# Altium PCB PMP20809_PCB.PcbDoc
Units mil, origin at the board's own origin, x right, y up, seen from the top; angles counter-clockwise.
Board outline 3600 x 1460 mil, 2 copper layers (Top Layer, Bottom Layer), stack 62 mil thick; 44 components, 29 nets, 110 pads, 38 vias.
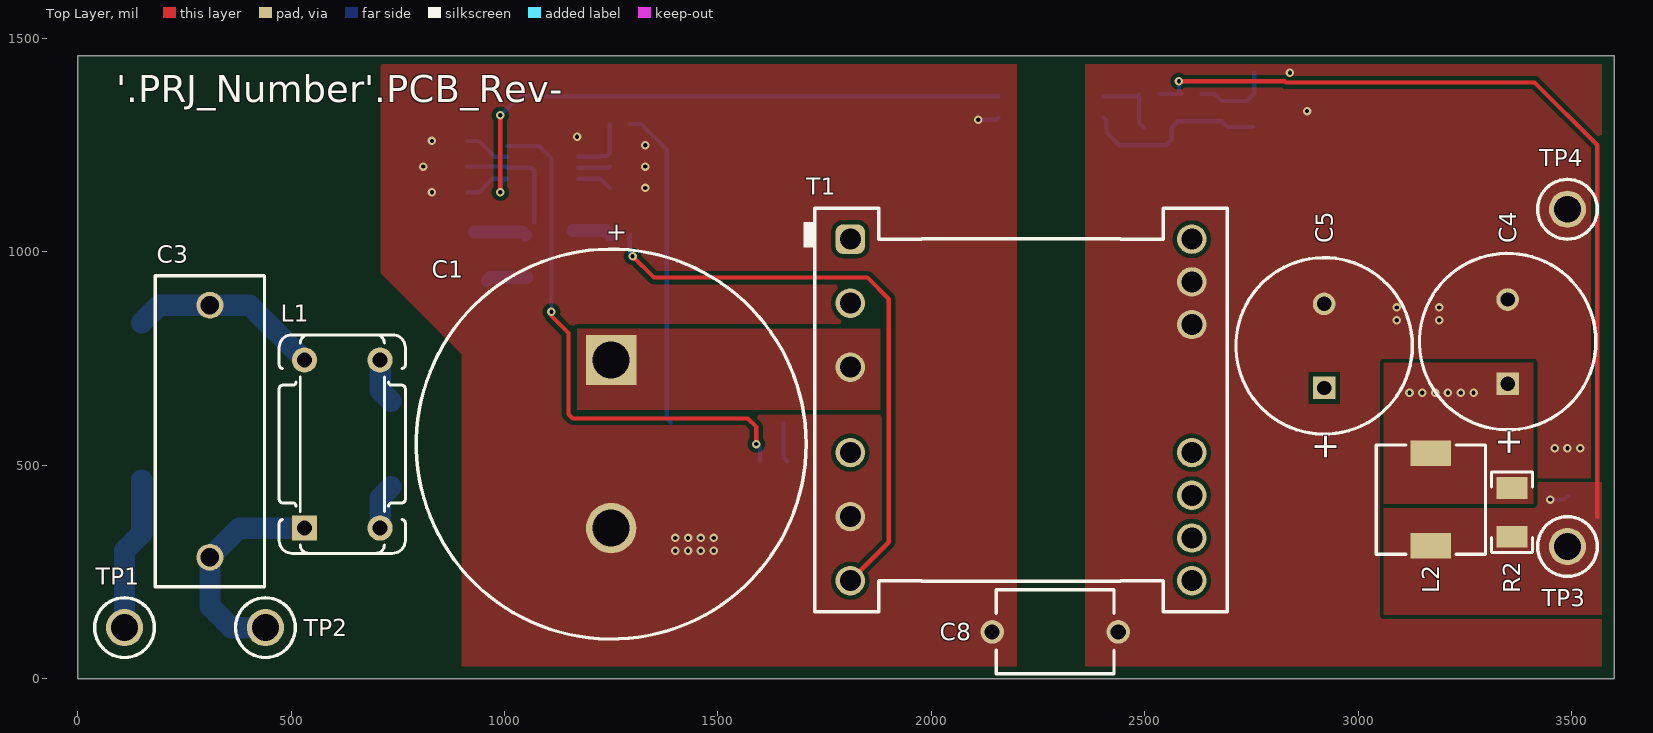
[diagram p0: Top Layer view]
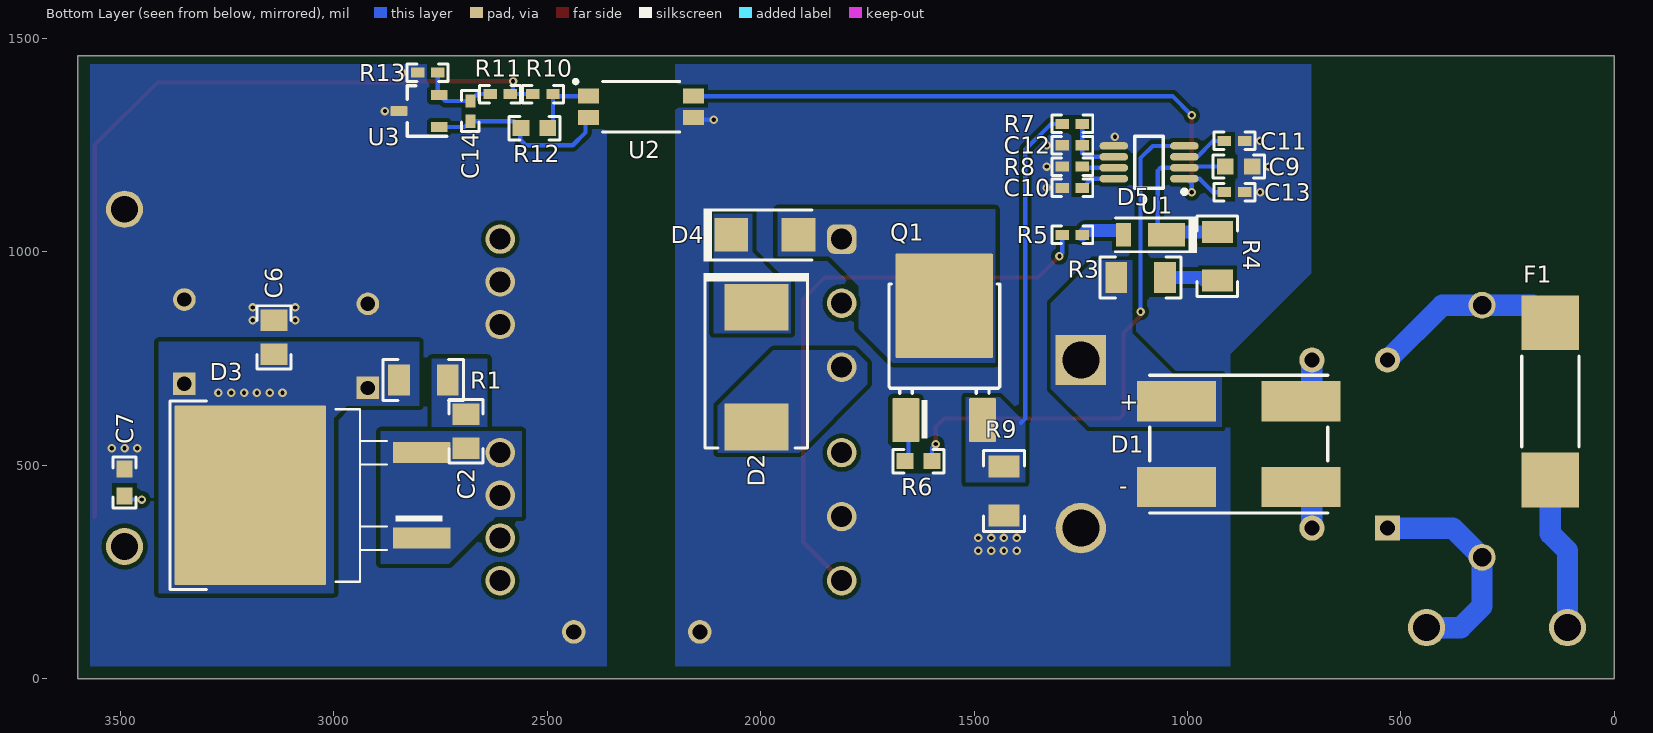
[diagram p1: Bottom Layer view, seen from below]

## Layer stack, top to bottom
Top Solder: solder mask 0.4, Solder Resist, Dk 3.5
Top Layer: signal copper 1.4
Dielectric1: core 59.2, FR-4, Dk 4.8
Bottom Layer: signal copper 1.4
Bottom Solder: solder mask 0.4, Solder Resist, Dk 3.5

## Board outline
0,0 3600,0 3600,1460 0,1460

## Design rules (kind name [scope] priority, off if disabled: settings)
AcuteAngle [All] p1: minimum=4.50000000000000E+0001 checktracksonly=FALSE
AssemblyTestPointUsage [All] p1: valid=2
Clearance Clearance_BoardEdge_MountingHoles [OnCopper and InComponentClass('Mounting Holes') vs IsKeepOut] p1: gap=40
Clearance Clearance_BoardEdge_Poly [OnCopper and InPoly vs IsKeepOut] p2: gap=25
Clearance Clearance_BoardEdge [OnCopper and Not InComponentClass('Logo') and not InComponentClass('FiducialMark') and not InRegion(1000,500,4000,800) and Not IsKeepout vs IsKeepOut] p3: gap=75
Clearance Clearance_Poly [InPolygon] p4: gap=10
Clearance [All] p5: gap=8
ComponentClearance ComponentClearance_ScrewToNut [(HasFootprint('NY PMS 440 0025 PH')) vs (HasFootprint('Keystone_1902C'))] p1: gap=5 collisioncheckmode=3 verticalgap=10 showdistances=FALSE
ComponentClearance ComponentClearance_MountingHoles [InComponentClass('Mounting Holes')] p2: gap=20 collisioncheckmode=3 verticalgap=100000 showdistances=FALSE
ComponentClearance ComponentClearance_SmallPassives [HasFootprint('0201*') or HasFootprint('0402*') or HasFootprint('0508') or HasFootprint('0603*') or HasFootprint('0612') or HasFootprint('0805*') or HasFootprint('0815*') or HasFootprint('0830*') or HasFootprint('1206*') or HasFootprint('1210*') or HasFootprint('1808*') or HasFootprint('1812*') or HasFootprint('1825*') or HasFootprint('2010*') or HasFootprint('2220*') or HasFootprint('2225*') or HasFootprint('2512*') or HasFootprint('2728*') or HasFootprint('3518*') vs HasFootprint('0201*') or HasFootprint('0402*') or HasFootprint('0508') or HasFootprint('0603*') or HasFootprint('0612') or HasFootprint('0805*') or HasFootprint('0815*') or HasFootprint('0830*') or HasFootprint('1206*') or HasFootprint('1210*') or HasFootprint('1808*') or HasFootprint('1812*') or HasFootprint('1825*') or HasFootprint('2010*') or HasFootprint('2220*') or HasFootprint('2225*') or HasFootprint('2512*') or HasFootprint('2728*') or HasFootprint('3518*')] p3: gap=10 collisioncheckmode=3 verticalgap=10 showdistances=FALSE
ComponentClearance ComponentClearance_THtoSMT [IsThruComponent vs IsSMTComponent] p4: gap=20 collisioncheckmode=3 verticalgap=100000 showdistances=FALSE
ComponentClearance ComponentClearance_THtoTH [IsThruComponent vs IsThruComponent] p5: gap=20 collisioncheckmode=3 verticalgap=100000 showdistances=FALSE
ComponentClearance [All] p6: gap=20 collisioncheckmode=3 verticalgap=10 showdistances=FALSE
DiffPairsRouting [All] p1: maxlimit=100 minlimit=10 mostfreqgap=10 toplayer_minwidth=15 toplayer_maxwidth=15 toplayer_prefwidth=15 bottomlayer_minwidth=15 bottomlayer_maxwidth=15 bottomlayer_prefwidth=15 maxuncoupledlength=1000
FabricationTestPointUsage TestPointUsage [All] p1: valid=2 allowmultiple=FALSE
FabricationTestpoint Testpoint [All] p1: side=3 testpointundercomponent=TRUE minsize=40 maxsize=100 preferedsize=60 minholesize=0 maxholesize=40 preferedholesize=32 testpointgrid=1 allowsidetop=TRUE allowsidebottom=TRUE usegrid=TRUE gridtolerance=0.01
FanoutControl Fanout_LCC [IsLCC] p1: bgadir=Out bgaviamode=Centered fanoutstyle=Auto fanoutdirection=Alternating viagrid=1 // Fanout_LCC (Default Rule)
FanoutControl Fanout_BGA [IsBGA] p2: bgadir=Out bgaviamode=Centered fanoutstyle=Auto fanoutdirection=Alternating viagrid=1 // Fanout_BGA (Default Rule)
FanoutControl Fanout_Default [All] p4: bgadir=Out bgaviamode=Centered fanoutstyle=Auto fanoutdirection=Alternating viagrid=1 // Fanout_Default (Default Rule)
FanoutControl Fanout_Small [(CompPinCount < 5)] p5: bgadir=Out bgaviamode=Centered fanoutstyle=Auto fanoutdirection=OutThenIn viagrid=1 // Fanout_Small (Default Rule)
HoleSize [All] p1: absolutevalues=TRUE maxlimit=251 minlimit=7 maxpercent=80.000 minpercent=20.000
MinimumAnnularRing [All] p1: minimumring=5
MinimumSolderMaskSliver MinimumSolderMaskSliver_Logo [InComponentClass('Logo') vs InComponentClass('Logo')] p1: minsoldermaskwidth=0
MinimumSolderMaskSliver SilkscreenOverComponentPads [All] p2: minsoldermaskwidth=0
MinimumSolderMaskSliver [All] p3: minsoldermaskwidth=0
PlaneConnect [All] p1: planeconnectstyle=Direct reliefexpansion=10 reliefentries=4 reliefconductorwidth=10 reliefairgap=10
PolygonConnect [All] p1: connectstyle=Direct reliefconductorwidth=10 reliefentries=4 polygonreliefangle="90 Angle" airgapwidth=10
RoutingVias [All] p1: holewidth=16 width=34 viastyle="Through Hole" minholewidth=7 minwidth=19 maxholewidth=40 maxwidth=65
SMDToCorner [All] p1: distance=0
SilkToBoardRegionClearance [Not ((IsComment or IsDesignator) And (Hide <> 'False')) and not InRegion(1000,500,4000,800)] p1:
SilkToSilkClearance [All] p1: silktosilkclearance=0
SilkToSolderMaskClearance [IsPad] p1: minsilkscreentomaskgap=0 clearancetoexposedcopper=TRUE
SolderMaskExpansion [All] p1: expansion=3
Width [All] p1: maxlimit=100 minlimit=6 preferedwidth=10 checkconnectedcopper=TRUE
15 further rules are at their usual default settings.

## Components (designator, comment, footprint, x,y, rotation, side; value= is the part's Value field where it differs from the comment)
C1 "LLS2G820MELZ" Nichicon_2200x2500_Snap 1250,550 r270 top
C2 "GRM2165C1H101JA01D" 0805_HV 2690,580 r270 bottom
C3 "890324025017" WCAP-FTX2_1800x600x1200 310,580 r270 top
C4 "EKZE350ELL221MJC5S" Chemi-Con_1000x1250 3350,790 r90 top
C5 "EKZE350ELL221MJC5S" Chemi-Con_1000x1250 2920,780 r90 top
C6 "C2012X5R1V685K125AC" 0805_HV 3140,800 r90 bottom
C7 "C1608X5R1H104K080AA" 0603 3490,460 r90 bottom
C8 "DE2E3KY152MN3AM02F" KY_700x500x1000 2290,110 r180 top
C9 "GRM188R6YA106MA73" 0603 880,1200 r180 bottom
C10 "GRM155R71C224KA12D" 0402 1270,1150 r0 bottom
C11 "GRM155R61E105KA12D" 0402 890,1260 r180 bottom
C12 "GRM1555C1H101JA01D" 0402 1270,1250 r0 bottom
C13 "GRM1555C1H101JA01D" 0402 890,1140 r180 bottom
C14 "GRM155R71H103KA88D" 0402 2680,1330 r270 bottom
D1 "Z4DGP406L-HF" Z4-D 880,550 r180 bottom
D2 "SMCJ150A-TP" SMC 2010,730 r270 bottom
D3 "MBRB20200CTT4G" DDPAK 3040,430 r0 bottom
D4 "MURA160T3G" SMA 1990,1040 r180 bottom
D5 "DFLS1200-7" PowerDI123 1099.8,1040 r0 bottom
F1 "0443003.DR" FUSE_0443 150,650 r270 bottom
L1 "744821201" WE-CMB_XS 620,550 r90 top
L2 "B82462G4102M" B82462G4 3170,420 r270 top
Q1 "AOD4S60" DPAK 1570,740 r90 bottom
R1 "CRCW1206100RJNEA" 1206 2790,700 r0 bottom
R2 "CRCW12062R00FKEA" 1206 3360,390 r270 top
R3 "CRCW1206499KFKEA" 1206 1110,940 r0 bottom
R4 "CRCW1206499KFKEA" 1206 930,990 r270 bottom
R5 "CRCW04020000Z0ED" 0402 1270,1040 r0 bottom
R6 "CRCW06030000Z0EA" 0603 1630,510 r0 bottom
R7 "CRCW04021K00JNED" 0402 1270,1300 r0 bottom
R8 "CRCW040222K1FKED" 0402 1270,1200 r180 bottom
R9 "CSR1206FKR250" 1206 1430,440 r90 bottom
R10 "CRCW04024K99FKED" 0402 2510,1370 r0 bottom
R11 "CRCW0402162KFKED" 0402 2610,1370 r180 bottom
R12 "CRCW06031K00JNEA" 0603 2530,1290 r180 bottom
R13 "CRCW040218K7FKED" 0402 2780,1420 r180 bottom
T1 "RLTI-1228" Renco_RLTI-1228 2210,630 r0 top
TP1 "5012" Keystone5012 110,120 r90 top
TP2 "5012" Keystone5012 440,120 r90 top
TP3 "5010" Keystone5010 3490,310 r0 top
TP4 "5011" Keystone5011 3490,1100 r0 top
U1 "LM5021MM-2/NOPB" MUA08A_N 1090,1210 r0 bottom
U2 "VOS617A-7X001T" SSOP-4_VISHAY 2280,1340 r180 bottom
U3 "TL431AIDBZR" DBZ0003A_N 2800,1330 r0 bottom

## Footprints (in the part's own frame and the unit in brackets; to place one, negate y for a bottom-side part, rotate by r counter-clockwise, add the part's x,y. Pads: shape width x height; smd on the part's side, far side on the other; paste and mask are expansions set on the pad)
0402 [mm] "0402 from SM-752 data"
  rect 0.8x0.6 smd: 1(-0.6,0) 2(0.6,0)
  silkscreen extent -1.22,-0.52 1.22,0.52, body extent -0.55,-0.3 0.55,0.3, height 0.6
0603 [mm] "0603 from SM-752 data"
  rect 1x0.95 smd: 1(-0.8,0) 2(0.8,0)
  silkscreen extent -1.52,-0.69 1.52,0.69, body extent -0.87,-0.47 0.87,0.47, height 1
0805_HV [mil] "0805 with 30mil clearance between pads"
  rect 50x63 smd: 1(-40,0) 2(40,0)
  silkscreen extent -74,-40 74,40, body extent -43,-29 43,29, height 57
1206 [mm] "1206 from SM-752 data"
  rect 1.3x1.85 smd: 1(-1.45,0) 2(1.45,0)
  silkscreen extent -2.4,-1.21 2.4,1.21, body extent -1.7,-0.9 1.7,0.9, height 1.35
B82462G4 [mm] "EPCOS"
  rect 1.5x2.4 smd: 1(-2.75,0) 2(2.75,0)
  silkscreen extent -3.25,-3.25 3.25,3.25, body extent -3.15,-3.15 3.15,3.15, height 3
Chemi-Con_1000x1250 [mm] "TH, 2-Leads, Body 10x12.5mm, Pin Spacing 5mm"
  rect 1.35x1.35 hole 0.85: 1(-2.5,0)
  round 1.35 hole 0.85: 2(2.5,0)
  silkscreen extent -5.25,-5.25 5.25,5.25, body extent -5.25,-5.25 5.25,5.25, height 14
DBZ0003A_N [mm] "SOT23, 3-Leads, Body 2.9x1.3mm, Pitch 0.95mm, Lead Span 2.4mm, IPC Medium Density"
  rrect17% 1x0.6 smd: 1(-1.2,0.95) 2(-1.2,-0.95) 3(1.2,0)
  silkscreen extent -1.65,-1.5 0.7,1.5, body extent -1.26,-1.46 1.26,1.46, height 0.98
DDPAK [mil] "D2-PAK, 3-Pads, Body 9.7x10.4mm (max), TO-263AB, using Vishay Silionix recommended pad sizes"
  rrect8% 135x49.49 smd: 1(-246.06,100) 3(-246.06,-100)
  rrect1% 355x420 smd paste-181.1: 4(155.51,0)
  silkscreen extent -295,-220 344,220, body extent -295,-202 324,202, height 180
DPAK [mm] "D-PAK, 3-Pads, Body 6.22x6.73mm (max), TO-252AA using nominal STEP model"
  rrect6% 2.6x1.6 smd: 1(-3.4,2.28) 3(-3.4,-2.28)
  rrect2% 6.2x5.8 smd paste-2.9: 4(3.4,0)
  silkscreen extent -4.5,-3.3 4.7,3.28, body extent -3.86,-3.29 5.84,3.29, height 2.48
FUSE_0443 [mm] "LITTELFUSE"
  rect 3.25x3.43 smd: 1(-4.675,0) 2(4.675,0)
  silkscreen extent -2.7,-1.7 2.7,1.7, body extent -5.05,-1.56 5.05,1.56, height 3.12
Keystone5010 [mil] "Keystone Multipurpose loops"
  round 87 hole 63: 1(0,0)
  silkscreen extent -70,-70 70,70, body extent -63,-63 63,62, height 319
Keystone5011 [mil] "Keystone Multipurpose loops"
  round 87 hole 63: 1(0,0)
  silkscreen extent -70,-70 70,70, body extent -63,-63 63,62, height 319
Keystone5012 [mil] "Keystone Multipurpose loops"
  round 87 hole 63: 1(0,0)
  silkscreen extent -70,-70 70,70, body extent -63,-63 63,62, height 319
KY_700x500x1000 [mm] "TH, 2- Leads, Body 7x5mm, Pin Spacing 7.5mm"
  round 1.4 hole 0.9: 1(-3.75,0) 2(3.75,0)
  silkscreen extent -3.5,-2.5 3.5,2.5, body extent -4.05,-2.5 4.05,2.5, height 9.97
MUA08A_N [mm] "TSOP, 8-Leads, Body 3x3mm, Pitch 0.65mm, IPC Medium Density"
  oval 1.7x0.45 smd: 1(-2.1,0.975) 2(-2.1,0.325) 3(-2.1,-0.325) 4(-2.1,-0.975) 5(2.1,-0.975) 6(2.1,-0.325) 7(2.1,0.325) 8(2.1,0.975)
  silkscreen extent -2.22,-1.55 0.85,1.87, body extent -1.6,-1.6 1.6,1.6, height 1.09
Nichicon_2200x2500_Snap [mm]
  rrect3% 3x3 hole 2.2: 1(-5,0)
  round 3 hole 2.2: 2(5,0)
  silkscreen extent -11.6,-11.6 11.6,11.6, body extent -11.5,-11.5 11.51,11.5, height 27.01
PowerDI123 [mm] "Diodes Inc recommended land pattern, document number DS30628 Rev. 6-2"
  rect 2.2x1.4 smd: 1(-1.275,0)
  rect 0.9x1.4 smd: 2(1.275,0)
  silkscreen extent -3.1,-1.09 1.76,1.09, body extent -2.37,-0.96 1.53,0.97, height 1
Renco_RLTI-1228 [mm] "TH, 13-Leads, Body 966x945mil"
  rrect50% 1.75x1.75 hole 1.25: 1(-10.16,10.16)
  round 1.75 hole 1.25: 2(-10.16,6.35) 3(-10.16,2.54) 4(-10.16,-2.54) 5(-10.16,-6.35) 6(-10.16,-10.16) 7(10.16,-10.16) 8(10.16,-7.62) 9(10.16,-5.08) 10(10.16,-2.54) 12(10.16,5.08) 13(10.16,7.62) 14(10.16,10.16)
  silkscreen extent -12.95,-12 12.27,12, body extent -12.27,-12 12.27,12, height 23.49
SMA [mm] "Molded Diode, 2-Leads, Body 4.3x2.6mm, IPC Medium Density, based on OnSemi component dimensions and land pattern"
  rect 2x2 smd: 1(-2,0) 2(2,0)
  silkscreen extent -3.66,-1.57 2.79,1.57, body extent -2.6,-1.3 2.6,1.3, height 2.42
SMC [mil] "Molded Diode, 2-Leads, Body 6.9x5.8mm, IPC Medium Density, based on OnSemi component dimensions and land patterns"
  rect 110x150 smd: 1(-140.49,0) 2(140.49,0)
  silkscreen extent -221,-123 189,124, body extent -156,-116 157,116, height 91
SSOP-4_VISHAY [mm] "Vishay Recommened"
  rect 1.25x0.9 smd: 1(-3.125,0.635) 2(-3.125,-0.635) 3(3.125,-0.635) 4(3.125,0.635)
  silkscreen extent -3.98,-1.5 2.3,1.59, body extent -3.5,-1.45 3.5,1.45, height 2.42
WCAP-FTX2_1800x600x1200 [mm] "TH, 2-Leads, Body 18x6mm, Lead Spacing 15mm"
  round 1.6 hole 1.1: 1(-7.5,0) 2(7.5,0)
  silkscreen extent -9.25,-3.25 9.25,3.25, body extent -9.25,-3.25 9.25,3.25, height 12.5
WE-CMB_XS [mm] "WE-CMB Series Size XS"
  rect 1.5x1.5 hole 0.9: 1(-5,2.25)
  round 1.5 hole 0.9: 2(-5,-2.25) 3(5,-2.25) 4(5,2.25)
  silkscreen extent -6.5,-3.75 6.5,3.75, body extent -6.5,-3.75 6.5,3.75, height 16.24
Z4-D [mm] "SMD, 4-Leads, Body 8.1x10.5mm"
  rect 4.7x2.4 smd: 1(-3.7,2.55) 2(3.7,2.55) 3(3.7,-2.55) 4(-3.7,-2.55)
  silkscreen extent -5.3,-4.1 5.3,4.1, body extent -5.3,-4.1 5.3,4.1, height 1.56

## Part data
C1: "CAP, AL, 82 µF, 400 V, +/- 20%, TH"
C2: "CAP, CERM, 100 pF, 50 V, +/- 5%, C0G/NP0, 0805"
C3: "CAP, Film, 0.1 µF, 275 V, +/- 10%, TH"
C4 C5: "CAP, AL, 220 µF, 35 V, +/- 20%, TH"
C6: "CAP, CERM, 6.8 µF, 35 V, +/- 10%, X5R, 0805"
C7: "CAP, CERM, 0.1 µF, 50 V, +/- 10%, X5R, 0603"
C8: "CAP, CERM, 1500 pF,  V, +/- 20%, E, TH, 2- Leads, Body 7x5mm, Pin Spacing 7.5mm"
C9: "CAP, CERM, 10 µF, 35 V, +/- 20%, X5R, 0603"
C10: "CAP, CERM, 0.22 µF, 16 V, +/- 10%, X7R, 0402"
C11: "CAP, CERM, 1 µF, 25 V, +/- 10%, X5R, 0402"
C12 C13: "CAP, CERM, 100 pF, 50 V, +/- 5%, C0G/NP0, 0402"
C14: "CAP, CERM, 0.01 µF, 50 V, +/- 10%, X7R, 0402"
D1: "Diode, P-N-Bridge, 600 V, 4 A, Z4-D"
D2: "Diode, TVS, Uni, 150 V, 243 Vc, SMC"
D3: "Diode, Schottky, 200 V, 20 A, DDPAK"
D4: "Diode, Ultrafast, 600 V, 1 A, AEC-Q101, SMA"
D5: "Diode, Schottky, 200 V, 1 A, PowerDI123"
F1: "Fuse, 3 A, 250VAC/VDC, SMD"
L1: "Coupled inductor, 1 mH, 2 A, 0.045 ohm, TH"
L2: "Inductor, Shielded Drum Core, Ferrite, 1 µH, 3.4 A, 0.016 ohm, AEC-Q200 Grade 0, SMD"
Q1: "MOSFET, N-CH, 600 V, 4 A, DPAK"
R1: "RES, 100, 5%, 0.25 W, 1206"
R2: "RES, 2.00, 1%, 0.25 W, 1206"
R3 R4: "RES, 499 k, 1%, 0.25 W, 1206"
R5: "RES, 0, 5%, 0.063 W, 0402"
R6: "RES, 0, 5%, 0.1 W, 0603"
R7: "RES, 1.0 k, 5%, 0.063 W, 0402"
R8: "RES, 22.1 k, 1%, 0.063 W, 0402"
R9: "RES, 0.25, 1%, 0.5 W, 1206"
R10: "RES, 4.99 k, 1%, 0.063 W, 0402"
R11: "RES, 162 k, 1%, 0.063 W, 0402"
R12: "RES, 1.0 k, 5%, 0.1 W, 0603"
R13: "RES, 18.7 k, 1%, 0.063 W, 0402"
T1: "Transformer, 200 uH, TH"
TP1 TP2: "Test Point, Multipurpose, White, TH"
TP3: "Test Point, Multipurpose, Red, TH"
TP4: "Test Point, Multipurpose, Black, TH"
U1: "AC-DC Current Mode PWM Controller, 8-pin MSOP, Pb-Free"
U2: "Optocoupler, 3.75 kV, 80-160% CTR, SMT"
U3: "Adjustable Precision Shunt Regulator, 34 ppm / degC, 100 mA, -40 to 85 degC, 3-pin SOT-23 (DBZ), Green (RoHS & no Sb/Br)"

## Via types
v1: diameter 20, hole 10, Top Layer to Bottom Layer, tented both sides, 38 vias

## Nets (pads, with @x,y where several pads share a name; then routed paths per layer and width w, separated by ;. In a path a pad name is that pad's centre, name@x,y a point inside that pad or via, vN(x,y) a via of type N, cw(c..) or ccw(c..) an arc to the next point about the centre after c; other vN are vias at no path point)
24V: C7.1 L2.2 R2.2 R10.2 R11.2 TP3.1 | length 2041.1
  Top Layer w10: v1(2580,1400) 2827.47,1400 2830.47,1397 3413,1397 3560,1250 3560,380
  Bottom Layer w10: R10.2 R11.2 2580,1376.38 v1(2580,1400) ; v1(3450,420) 3481.5,420 C7.1
GND: C4.2 C5.2 C6.2 C7.2 C8.1 R13.1 T1.12 T1.13 TP4.1 U3.3
  other v1: 3460,540 3490,540 3520,540 3090,840 3190,840 3090,870 3190,870 2880,1330 2840,1420
NetC1_1: C1.1 D1.1 D2.2 R3.2 T1.3
NetC2_1: C2.1 R1.1
NetC2_2: C2.2 D3.1 D3.3 T1.9 T1.10
NetC3_1: C3.1 F1.1 L1.4 | length 451.7
  Bottom Layer w50: F1.1 191.22,875.28 C3.1 402.99,875.28 L1.4
NetC3_2: C3.2 L1.1 TP2.1 | length 515.2
  Bottom Layer w50: TP2.1 360,120 310,170 C3.2 378.43,353.15 L1.1
NetC4_1: C4.1 C5.1 C6.1 D3.4 L2.1 R1.2 R2.1
  other v1: 3120,670 3150,670 3180,670 3210,670 3240,670 3270,670
NetC9_1: C9.1 D5.1 R4.1 U1.2 | length 405.4
  Bottom Layer w10: C9.1 1004.53,1200 U1.2 1062.8,1197.2 1070,1190 1070,1069.8
  Bottom Layer w30: R4.1 1042.52,1047.09 D5.1
NetC10_1: C10.1 U1.8 | length 82.7
  Bottom Layer w10: U1.8 1224.76,1171.61 C10.1
NetC11_1: C11.1 U1.3 | length 109.1
  Bottom Layer w10: C11.1 940,1260 977.2,1222.8 U1.3
NetC12_1: C12.1 R7.1 U1.6 | length 146.2
  Bottom Layer w10: U1.6 1223.23,1222.8 1225.25,1224.81 1240.31,1224.81 1246.38,1230.88 C12.1 R7.1
NetC13_1: C13.1 U1.1 U2.4 | length 1508.8
  Top Layer w10: v1(990,1140) v1(990,1320)
  Bottom Layer w10: C13.1 940,1140 971.61,1171.61 U1.1@1001.61,1171.61 ; v1(990,1140) 990,1160 U1.1@1001.61,1171.61 ; v1(990,1320) 1035,1365 U2.4 ; U1.1 U1.1@1001.61,1171.61
NetC14_1: C14.1 R11.1 R13.2 U3.2 | length 185.7
  Bottom Layer w10: R11.1 2663.62,1370 C14.1 2738.98,1353.62 U3.2 2756.38,1371.02 R13.2
NetC14_2: C14.2 R12.1 U2.2 U3.1 | length 439.9
  Bottom Layer w10: U2.2 2410,1308.03 2410,1280 2440,1250 2550,1250 2562.8,1262.8 2562.8,1288.7 R12.1 2577.87,1306.38 C14.2 2693.78,1292.6 U3.1
NetD1_2: D1.2 L1.3 | length 107.1
  Bottom Layer w50: L1.3 708.58,676.14 D1.2
NetD1_3: D1.3 L1.2 | length 107.1
  Bottom Layer w50: L1.2 708.58,423.86 D1.3
NetD2_1: D2.1 D4.1
NetD4_2: D4.2 Q1.4 T1.1
NetD5_2: D5.2 R5.1 | length 90.3
  Bottom Layer w30: D5.2@1160.2,1050 1236.38,1050 R5.1
NetF1_2: F1.2 TP1.1 | length 362.5
  Bottom Layer w50: TP1.1 110,300 150,340 F1.2
NetQ1_1: Q1.1 R6.2 | length 93.3
  Bottom Layer w10: Q1.1@1653.62,600 1653.62,517.87 R6.2
NetQ1_3: Q1.3 R7.2 R9.2 | length 755.4
  Bottom Layer w10: R7.2 1320,1300 1380,1240 1380,610 1390,600
NetR3_1: R3.1 R4.2 | length 95.8
  Bottom Layer w30: R4.2@960,932.91 967.09,940 R3.1
NetR5_2: R5.2 T1.6 | length 1391.3
  Top Layer w10: v1(1300,990) 1350,940 1850,940 1900,890 1900,320 T1.6
  Bottom Layer w10: R5.2 1293.62,996.38 v1(1300,990)
NetR6_1: R6.1 U1.4 | length 1267
  Top Layer w10: v1(1110,860) 1110,850 1150,810 1150,620 1160,610 1570,610 1590,590 v1(1590,550)
  Bottom Layer w10: U1.4 1081.61,1248.39 1110,1220 v1(1110,860) ; v1(1590,550) 1598.5,541.5 R6.1
NetR8_2: R8.2 U1.7 | length 74.9
  Bottom Layer w10: U1.7 1243.58,1197.2 R8.2
NetR10_1: R10.1 R12.2 U2.1 | length 170.4
  Bottom Layer w10: U2.1 2481.38,1365 R10.1 2486.38,1302.13 R12.2
PGND: C1.2 C8.2 C9.2 C10.2 C11.2 C12.2 C13.2 D1.4 R8.1 R9.1 T1.5 U1.5 U2.3 | length 49
  Bottom Layer w10: v1(2110,1310) 2151.97,1310 U2.3
  other v1: 1400,300 1430,300 1460,300 1490,300 1400,330 1430,330 1460,330 1490,330 830,1140 1330,1150 810,1200 1330,1200 1330,1250 830,1260 1170,1270
pads on no net: T1.2 T1.4 T1.7 T1.8 T1.14

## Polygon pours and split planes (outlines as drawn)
GND on Top Layer "TOP_LAYER_GND_P030" (solid, remove dead copper, pour order 30): 2360,30 3570,30 3570,1440 2360,1440 2360,30
PGND on Top Layer "TOP_LAYER_PGND_P022" (solid, remove dead copper, pour order 22): 900,1440 700,1440 710,1430 710,950 900,760 900,30 2200,30 2200,1440 710,1440
24V on Top Layer "TOP_LAYER_24V_P020" (solid, remove dead copper, pour order 20): 3060,460 3060,150 3540,150 3570,150 3570,460
NetC4_1 on Top Layer "TOP_LAYER_NETC4_1_P018" (solid, remove dead copper, pour order 18): 3060,590 3060,410 3410,410 3410,740 3060,740 3060,580
NetC1_1 on Top Layer "TOP_LAYER_NETC1_1_P001" (solid, remove dead copper, pour order 1): 1170,820 1170,630 1880,630 1880,820 1170,820
NetC2_1 on Bottom Layer "BOTTOM_LAYER_NETC2_1_P000" (solid, remove dead copper, pour order 0): 2640,750 2640,590 2770,590 2770,750 2640,750
GND on Bottom Layer "BOTTOM_LAYER_GND_P026" (solid, remove dead copper, pour order 26): 2360,30 2360,1440 3570,1440 3570,30 2360,30
PGND on Bottom Layer "BOTTOM_LAYER_PGND_P024" (solid, remove dead copper, pour order 24): 710,950 900,760 900,30 2200,30 2200,1440 710,1440 710,950
NetC4_1 on Bottom Layer "BOTTOM_LAYER_NETC4_1_P016" (solid, remove dead copper, pour order 16): 2800,790 2800,640 2950,640 2970,640 3000,610 3000,200 3410,200 3410,520 3410,790 2800,790
NetC2_2 on Bottom Layer "BOTTOM_LAYER_NETC2_2_P014" (solid, remove dead copper, pour order 14): 2560,580 2560,380 2620,380 2730,270 2890,270 2890,580 2560,580
NetD4_2 on Bottom Layer "BOTTOM_LAYER_NETD4_2_P004" (solid, remove dead copper, pour order 4): 1450,1100 1450,740 1690,740 1770,820 1770,910 1770,920 1830,980 1840,990 1960,990 1960,1100
NetQ1_3 on Bottom Layer "BOTTOM_LAYER_NETQ1_3_P006" (solid, remove dead copper, pour order 6): 1380,460 1520,460 1520,660 1440,660 1380,600
NetC1_1 on Bottom Layer "BOTTOM_LAYER_NETC1_1_P008" (solid, remove dead copper, pour order 8): 1930,530 2100,530 2100,640 1970,770 1780,770 1750,740 1750,690 1910,530
NetD2_1 on Bottom Layer "BOTTOM_LAYER_NETD2_1_P010" (solid, remove dead copper, pour order 10): 2020,1090 2020,1000 1960,940 1930,940 1930,810 2110,810 2110,1090
NetC1_1 on Bottom Layer "BOTTOM_LAYER_NETC1_1_P012" (solid, remove dead copper, pour order 12): 920,710 920,590 1230,590 1320,680 1320,850 1320,880 1220,980 1130,980 1130,810 1031.42,711.42 920,711.42

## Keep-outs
Keep-Out Layer:
  text ".Layer_Name" at 577,-858.49 h60

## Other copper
Top Layer:
  text ".Layer_Name" at 577,-858.49 h60
Bottom Layer:
  text ".Layer_Name" at 577,-858.49 h60

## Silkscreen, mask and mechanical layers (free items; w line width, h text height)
Top Overlay:
  text "'.PRJ_Number'.PCB_Rev-" at 90,1330 h108.27
  text ".Layer_Name" at 577,-858.49 h60
Bottom Overlay:
  text ".Layer_Name" at 577,-858.49 h60
Top Paste:
  text ".Layer_Name" at 577,-858.49 h60
Bottom Paste:
  text ".Layer_Name" at 577,-858.49 h60
Top Solder:
  text ".Layer_Name" at 577,-858.49 h60
  text ".Layer_Name" at 577,-858.49 h60
Bottom Solder:
  text ".Layer_Name" at 577,-858.49 h60
Drill Guide:
  text ".Layer_Name" at 577,-858.49 h60
M1 Board Outline:
  the board outline again, w10
  text ".Layer_Name" at 577,-858.49 h60
M2 Board Dimensions:
  rectangle: 125,-400 500,-275
  rectangle: 0,-275 125,-150
  lines w7: 0,-275 1000,-275 ; 125,-400 125,-150 ; 250,-400 250,-150 ; 500,-400 500,-150 ; 750,-400 750,-150 ; 0,-400 0,-150 1000,-150 1000,-400 0,-400
  text ".Layer_Name" at 577,-858.49 h60
M3 3D STEP Top:
  text ".Layer_Name" at 577,-858.49 h60
M4 3D STEP Bottom:
  text ".Layer_Name" at 577,-858.49 h60
M5 Assembly Top:
  lines w10: -292,-930.17 6308,-930.17 ; -292,-726.83 6310,-726.83 ; -292,-523.5 -292,-1133.5 3713,-1133.5 6310,-1133.5 6310,-523.5 -291.5,-523.5 -291.5,-1133.5 1284,-1133.5 ; 2173,-1133.5 2173,-523.5 ; 3440,-726.83 3440,-523.5 ; 4280,-726.83 4280,-523.5 ; 4902,-1140 4902,-937.17
  text "COMPONENTS MARKED 'DNP' SHOULD NOT BE POPULATED." at 1153.5,-318.5 h60
  text "ASSEMBLY VARIANT:" at 1153,-434 h60
  text ".VariantName" at 2189,-434 h60
  text "PCB VIEWED FROM TOP SIDE" at -228.5,-655.67 h60
  text "BOARD #:" at 2248,-655.67 h60
  text ".PRJ_Number" at 2793.5,-655.67 h60
  text "REV:" at 3638,-655.67 h60
  text ".PCB_Rev" at 3929.5,-655.67 h60
  text "SVN REV:" at 4476,-655.67 h60
  text ".VersionControl_RevNumber" at 4982,-655.67 h60
  text "TID #:" at 2248,-859 h60
  text ".TID" at 2793.5,-859 h60
  text "PLOT NAME =" at -228.5,-1064.34 h60
  text ".plot_File_Name" at 577,-1064.34 h60
  text "GENERATED    :" at 2250,-1064.34 h60
  text ".Print_Date" at 3119.5,-1064.34 h60
  text ".Print_Time" at 3848.5,-1064.34 h60
  text "TEXAS INSTRUMENTS" at 5113,-1064.34 h60
M6 Assembly Bottom:
  lines w10: -292.5,-727.33 6309.5,-727.33 ; -290.5,-930.67 6309.5,-930.67 ; 1115.5,-1140.5 1115.5,-937.67 ; 1737.5,-727.33 1737.5,-524 ; 2577.5,-727.33 2577.5,-524 ; 3844.5,-1134 3844.5,-524 ; 4733.5,-1134 6309,-1134 6309,-524 -292.5,-524 -292.5,-1134 2304.5,-1134 6309.5,-1134 6309.5,-524
  text "COMPONENTS MARKED 'DNP' SHOULD NOT BE POPULATED." at 6102,-318 h60
  text ".VariantName" at 5058,-434 h60
  text "ASSEMBLY VARIANT:" at 6097,-434 h60
  text ".VersionControl_RevNumber" at 1035.5,-656.17 h60
  text "SVN REV:" at 1541.5,-656.17 h60
  text ".PCB_Rev" at 2088,-656.17 h60
  text "REV:" at 2379.5,-656.17 h60
  text ".PRJ_Number" at 3224,-656.17 h60
  text "BOARD #:" at 3769.5,-656.17 h60
  text "PCB VIEWED FROM BOTTOM SIDE" at 6246,-656.17 h60
  text ".TID" at 3224,-859.5 h60
  text "TID #:" at 3769.5,-859.5 h60
  text "TEXAS INSTRUMENTS" at 904.5,-1064.84 h60
  text ".Print_Time" at 2169,-1064.84 h60
  text ".Print_Date" at 2898,-1064.84 h60
  text "GENERATED    :" at 3767.5,-1064.84 h60
  text ".plot_File_Name" at 5440.5,-1064.84 h60
  text "PLOT NAME =" at 6246,-1064.84 h60
M9 Title Sheet:
  drawing of 57 lines, arcs and shapes, not listed
  text "1" at 739.84,8036.5 h70
  text "2" at 3235.5,8036.5 h70
  text "3" at 5724.84,8036.5 h70
  text "4" at 8231.51,8036.5 h70
  text "5" at 10730.5,8036.5 h70
  text "6" at 13235.5,8036.5 h70
  text "A" at -416.5,6893.5 h70
  text "A" at 14383.5,6893.5 h70
  text "B" at -416.5,4513.5 h70
  text "B" at 14383.5,4513.5 h70
  text "C" at -416.5,2138.5 h70
  text "C" at 14383.5,2138.5 h70
  text "PROJECT TITLE:" at 11343.5,277.5 h45
  text ".PRJ_Title" at 11393.5,144.17 h70
  text "DESIGNED FOR:" at 11343.5,-23.5 h45
  text ".PRJ_Customer" at 11393.5,-163.5 h70
  text "D" at -416.5,-231.5 h70
  text "D" at 14383.5,-231.5 h70
  text "FILE NAME:" at 11343.5,-323.5 h45
  text ".PCB_File_Name_No_Path" at 11393.5,-443.5 h70
  text "Texas Instruments (TI) and/or its licensors do not warrant the accuracy or completeness of this specification" at 6374,-605.34 h45
  text "ENGINEER:" at 11343.5,-613.5 h45
  text "LAYOUT BY:" at 12848.5,-613.5 h45
  text "or any information contained therein. TI and/or its licensors do not warrant that this design will meet" at 6329.01,-718 h45
  text ".PRJ_Engineer" at 11393.5,-768.49 h70
  text ".PCB_Layout" at 12899,-768.49 h70
  text "the specifications, will be suitable for your application or fit for any particular purpose, or will operate in" at 6329.01,-830.67 h45
  text ".Layer_Name" at 577,-858.49 h60
  text "ALTIUM DESIGNER VERSION:" at 12848.5,-923.5 h45
  text "an implementation. TI and/or its licensors do not warrant that the design is production worthy. You should" at 6329.01,-943.33 h45
  text "completely validate and test your design implementation to confirm the system functionality for your application." at 6374,-1056 h45
  text ".print_Scale" at 11393.5,-1056.83 h70
  text ".Application_BuildNumber" at 12899,-1056.83 h70
  text "1" at 739.84,-1263.5 h70
  text "2" at 3235.5,-1263.5 h70
  text "3" at 5724.84,-1263.5 h70
  text "4" at 8231.51,-1263.5 h70
  text "5" at 10730.5,-1263.5 h70
  text "6" at 13235.5,-1263.5 h70
M10 Fab Notes:
  drawing of 173 lines, arcs and shapes, not listed
  text "DESIGN INFORMATION" at 12378.02,6201 h60
  text "MIN. TRACK WIDTH:" at 11733.46,6021 h60
  text "8" at 12829.7,6021 h60
  text "MIL" at 12984.46,6021 h60
  text "MIN. CLEARANCE:" at 11733.46,5889 h60
  text "0.2" at 12769.7,5889 h60
  text "mm" at 12984.46,5889 h60
  text "MIN. VIA PAD SIZE:" at 11733.46,5757 h60
  text "24" at 12799.71,5757 h60
  text "MIL" at 12984.46,5757 h60
  text "0.05mm (2MIL)" at 12428.46,5615.29 h60
  text "MINIMUM ANNULAR RING" at 11404.23,5611 h60
  text "EXTERNAL" at 13136.46,5611 h60
  text "PER" at 11604.23,5493 h60
  text "IPC-D-275 CLASS 2 LEVEL C" at 11824.23,5493 h60
  text "MIL, HOLES" at 13312.46,5380.71 h60
  text "+/-" at 12920,5380 h60
  text "+/-" at 13774,5380 h60
  text "REGISTRATION TOLERANCES:" at 11404.23,5375 h60
  text "METAL" at 12604,5375 h60
  text "5" at 13180.2,5375 h60
  text "3" at 14013.2,5375 h60
  text "MIL" at 14129.46,5375 h60
  text "+/-" at 13774,5262 h60
  text "HOLE SIZE TOLERANCE (UNLESS OTHERWISE SPECIFIED):" at 11404.23,5257 h60
  text "3" at 14013.2,5257 h60
  text "MIL" at 14129.46,5257 h60
  text "MATERIAL:" at 11329.46,5047.54 h60
  text "FR-4 High Tg" at 12315.9,4907.21 h60
  text "FR-408" at 11750.46,4898.64 h60
  text "OTHER" at 13238.46,4898.64 h60
  text "X" at 12161,4895 h60
  text "62 MIL (1.6mm) +/-10%" at 12070.56,4735.92 h60
  text "THICKNESS:" at 11404.23,4731.64 h60
  text "X" at 11942.4,4731.64 h60
  text "OTHER" at 13355.46,4731.64 h60
  text "TOLERANCE:" at 11404.23,4573.64 h60
  text "X" at 12243.53,4573.64 h60
  text "ANSI IPC-6012 TYPE 3 CLASS 2" at 12430.48,4573.64 h60
  text "OTHER +/-" at 12430.46,4417.64 h60
  text "BOW & TWIST:" at 11404.23,4260.64 h60
  text "X" at 12243.53,4260.64 h60
  text "ANSI IPC-6012 TYPE 3 CLASS 2" at 12430.48,4260.64 h60
  text "OTHER +/-" at 12430.46,4102.13 h60
  text "DRILLING:" at 11329.46,3963.64 h60
  text "REFERENCE:" at 11404.23,3846.64 h60
  text "X" at 12052.46,3846.64 h60
  text "AS SHOWN" at 12239.46,3846.64 h60
  text "X" at 12953.46,3846.64 h60
  text "NC_DRILL FILES" at 13090.46,3846.64 h60
  text "PTH COPPER THICKNESS:" at 11404.23,3688.64 h60
  text "X" at 12534.46,3688.64 h60
  text "20-30 um" at 12671.46,3688.64 h60
  text "OTHER" at 13388.46,3688.64 h60
  text "BOARD FINISH:" at 11329.46,3529.64 h60
  text "SILKSCREEN:" at 11484.68,3411.64 h60
  text "X" at 12433.46,3411.64 h60
  text "TOP" at 12559.46,3411.64 h60
  text "X" at 12943.46,3411.64 h60
  text "BOTTOM" at 13070.46,3411.64 h60
  text "SILKSCREEN COLOR:" at 11484.68,3244.64 h60
  text "X" at 12432.42,3244.64 h60
  text "WHITE" at 12559.46,3244.64 h60
  text "OTHER" at 13070.46,3244.64 h60
  text "X" at 13170,3090 h60
  text "GREEN" at 12690.46,3085.44 h60
  text "OTHER" at 13308.46,3085.44 h60
  text "BLUE" at 13650,3080 h60
  text "SOLDER RESIST COLOR:" at 11484.68,3074.64 h60
  text "X" at 12563.42,2915.44 h60
  text "MATTE" at 12690.46,2915.44 h60
  text "SEMI-GLOSS" at 13308,2914.8 h60
  text "IMMERSION GOLD (ENIG)" at 12390.46,2726.92 h60
  text "ENEPIG" at 13728,2723.64 h60
  text "SURFACE FINISH:" at 11329.46,2722.64 h60
  text "X" at 12203.51,2722.64 h60
  text "IMM. TIN/SILVER OR EQUIV" at 11659,2565.64 h60
  text "OTHER" at 13090.46,2565.64 h60
  text "ARRAY/PANEL:" at 11329.46,2386.64 h60
  text "CUT AND TRIM PER M1 BOARD OUTLINE" at 12390.46,2382.35 h60
  text "N.C. ROUTE" at 12390.46,2230.64 h60
  text "X" at 13069.46,2230.64 h60
  text "V. SCORE" at 13256.46,2230.64 h60
  text "CERTIFICATION:" at 11329.46,2093.64 h60
  text "MATERIALS AND WORKMANSHIP FOR ALL PCBS" at 12054.46,2093.64 h60
  text "TO MEET OR EXCEED THE REQUIREMENTS OF:" at 12054.46,1995.64 h60
  text "X" at 11680.96,1859.13 h60
  text "ANSI IPC-A-600F CLASS ->" at 11819.96,1859.13 h60
  text "X" at 13459.02,1859.13 h60
  text "2" at 13577.96,1859.14 h60
  text "1" at 13262.96,1857.64 h60
  text "3" at 13931.96,1857.64 h60
  text "X" at 12495.02,1699.64 h60
  text "RoHS" at 12631.96,1699.64 h60
  text "OTHER" at 13276.36,1699.64 h60
  text "PER ORDER" at 13673.42,1699.64 h60
  text "ALL BOARDS MUST MEET OR EXCEED UL94-V0 REQUIREMENTS." at 11357,1534 h60
  text "PCB MUST BEAR THE UL94V-0 UL REGISTERED MATERIAL ID NUMBER" at 11357,1414 h60
  text "ADDITIONAL REQUIREMENTS:" at 11329.46,1240.64 h60
  text "MICROSECTION:" at 11404.23,1125.64 h60
  text "YES" at 12309.96,1125.64 h60
  text "X" at 12570,990 h60
  text "REQUIRED" at 13171.46,969.49 h60
  text "BARE BOARD ELEC. TEST:" at 11404.23,966.64 h60
  text "NONE" at 12709.96,966.64 h60
  text "PER ORDER" at 13763.46,966.64 h60
  text ".Layer_Name" at 577,-858.49 h60
M11 Gerber Information:
  lines w10: -292,-930.17 6308,-930.17 ; -292,-726.83 6310,-726.83 ; -292,-523.5 -292,-1133.5 3713,-1133.5 6310,-1133.5 6310,-523.5 -291.5,-523.5 -291.5,-1133.5 1284,-1133.5 ; 2173,-1133.5 2173,-523.5 ; 3440,-726.83 3440,-523.5 ; 4280,-726.83 4280,-523.5 ; 4902,-1140 4902,-937.17
  text "ALL ARTWORK VIEWED FROM TOP SIDE" at -228.5,-655.67 h60
  text "BOARD #:" at 2248,-655.67 h60
  text ".PRJ_Number" at 2793.5,-655.67 h60
  text "REV:" at 3638,-655.67 h60
  text ".PCB_Rev" at 3929.5,-655.67 h60
  text "SVN REV:" at 4476,-655.67 h60
  text ".VersionControl_RevNumber" at 4982,-655.67 h60
  text "LAYER NAME =" at -228.5,-858.49 h60
  text "TID #:" at 2248,-859 h60
  text ".TID" at 2793.5,-859 h60
  text "PLOT NAME =" at -228.5,-1064.34 h60
  text ".plot_File_Name" at 577,-1064.34 h60
  text "GENERATED    :" at 2250,-1064.34 h60
  text ".Print_Date" at 3119.5,-1064.34 h60
  text ".Print_Time" at 3848.5,-1064.34 h60
  text "TEXAS INSTRUMENTS" at 5113,-1064.34 h60
M12 Stackup:
  drawing of 191 lines, arcs and shapes, not listed
  text "Layer" at 9770.09,7800 h60
  text "Name" at 10180,7800 h60
  text "Material" at 11109.74,7800 h60
  text "Thickness" at 11969.51,7800 h60
  text "Constant" at 12619.35,7800 h60
  text "Board Layer Stack" at 13189.21,7800 h60
  text "1" at 9770.09,7680 h60
  text "Top Overlay" at 10180,7680 h60
  text "2" at 9770.09,7560 h60
  text "Top Solder" at 10180,7560 h60
  text "Solder Resist" at 11109.74,7560 h60
  text "0.40mil" at 11969.51,7560 h60
  text "3.5" at 12619.35,7560 h60
  text "3" at 9770.09,7440 h60
  text "Top Layer" at 10180,7440 h60
  text "Copper" at 11109.74,7440 h60
  text "1.40mil" at 11969.51,7440 h60
  text "4" at 9770.09,7320 h60
  text "Dielectric1" at 10180,7320 h60
  text "FR-4" at 11109.74,7320 h60
  text "59.20mil" at 11969.51,7320 h60
  text "4.8" at 12619.35,7320 h60
  text "5" at 9770.09,7200 h60
  text "Bottom Layer" at 10180,7200 h60
  text "Copper" at 11109.74,7200 h60
  text "1.40mil" at 11969.51,7200 h60
  text "6" at 9770.09,7080 h60
  text "Bottom Solder" at 10180,7080 h60
  text "Solder Resist" at 11109.74,7080 h60
  text "0.40mil" at 11969.51,7080 h60
  text "3.5" at 12619.35,7080 h60
  text "7" at 9770.09,6960 h60
  text "Bottom Overlay" at 10180,6960 h60
  text ".Layer_Name" at 577,-858.49 h60
M13 Component Bodies Top:
  text ".Layer_Name" at 577,-858.49 h60
M14 Component Bodies Bottom:
  text ".Layer_Name" at 577,-858.49 h60
M15 Courtyards Top:
  text ".Layer_Name" at 577,-858.49 h60
M16 Courtyards Bottom:
  text ".Layer_Name" at 577,-858.49 h60
Drill Drawing:
  circle w10: c3793.72,956.28 r27.63
  lines w10: 3766.09,182.74 3821.34,182.74 3821.34,237.99 3766.09,237.99 3766.09,182.74 ; 3766.09,362.31 3821.34,362.31 3793.72,307.06 3766.09,362.31 ; 3766.09,431.38 3793.72,445.19 3821.34,431.38 3807.53,459 3821.34,486.63 3793.72,472.82 3766.09,486.63 3779.9,459 3766.09,431.38 ; 3766.09,569.51 3779.9,569.51 3779.9,555.7 3807.53,555.7 3807.53,569.51 3821.34,569.51 3821.34,597.14 3807.53,597.14 3807.53,610.95 3779.9,610.95 3779.9,597.14 3766.09,597.14 3766.09,569.51 ; 3766.09,693.83 3779.9,693.83 3793.72,680.02 3807.53,693.83 3821.34,693.83 3807.53,707.64 3821.34,721.46 3807.53,721.46 3793.72,735.27 3779.9,721.46 3766.09,721.46 3779.9,707.64 3766.09,693.83 ; 3766.09,804.34 3766.09,818.15 3779.9,831.96 3766.09,845.78 3766.09,859.59 3779.9,859.59 3793.72,845.78 3807.53,859.59 3821.34,859.59 3821.34,845.78 3807.53,831.96 3821.34,818.15 3821.34,804.34 3807.53,804.34 3793.72,818.15 3779.9,804.34 3766.09,804.34
  lines w12: 3716,145.44 6947.49,145.44 ; 3716,1015.68 6947.49,1015.68 ; 4053.86,21.12 4053.86,1140 ; 4385.86,21.12 4385.86,1140 ; 5022.43,21.12 5022.43,1140 ; 5281.57,21.12 5281.57,1140 ; 5656.72,21.12 5656.72,1140 ; 6381.05,21.12 6381.05,1140 ; 3716,21.12 6947.49,21.12 6947.49,1140 3716,1140 3716,21.12
  text "Symbol" at 3790.59,1052.98 h72
  text "Quantity" at 4091.16,1052.98 h72
  text "Finished Hole Size" at 4423.16,1052.98 h72
  text "Plated" at 5059.72,1052.98 h72
  text "Hole Type" at 5318.86,1052.98 h72
  text "Drill Layer Pair" at 5694.02,1052.98 h72
  text "Hole Tolerance" at 6418.35,1052.98 h72
  text "38" at 4091.16,928.66 h60
  text "10.00mil (0.254mm)" at 4423.16,928.66 h60
  text "PTH" at 5059.72,928.66 h60
  text "Round" at 5318.86,928.66 h60
  text "Top Layer - Bottom Layer" at 5694.02,928.66 h60
  text "4" at 4091.16,804.34 h60
  text "33.46mil (0.850mm)" at 4423.16,804.34 h60
  text "PTH" at 5059.72,804.34 h60
  text "Round" at 5318.86,804.34 h60
  text "Top Layer - Bottom Layer" at 5694.02,804.34 h60
  text "6" at 4091.16,680.02 h60
  text "35.43mil (0.900mm)" at 4423.16,680.02 h60
  text "PTH" at 5059.72,680.02 h60
  text "Round" at 5318.86,680.02 h60
  text "Top Layer - Bottom Layer" at 5694.02,680.02 h60
  text "2" at 4091.16,555.7 h60
  text "43.31mil (1.100mm)" at 4423.16,555.7 h60
  text "PTH" at 5059.72,555.7 h60
  text "Round" at 5318.86,555.7 h60
  text "Top Layer - Bottom Layer" at 5694.02,555.7 h60
  text "13" at 4091.16,431.38 h60
  text "49.21mil (1.250mm)" at 4423.16,431.38 h60
  text "PTH" at 5059.72,431.38 h60
  text "Round" at 5318.86,431.38 h60
  text "Top Layer - Bottom Layer" at 5694.02,431.38 h60
  text "4" at 4091.16,307.06 h60
  text "63.00mil (1.600mm)" at 4423.16,307.06 h60
  text "PTH" at 5059.72,307.06 h60
  text "Round" at 5318.86,307.06 h60
  text "Top Layer - Bottom Layer" at 5694.02,307.06 h60
  text "2" at 4091.16,182.74 h60
  text "86.61mil (2.200mm)" at 4423.16,182.74 h60
  text "PTH" at 5059.72,182.74 h60
  text "Round" at 5318.86,182.74 h60
  text "Top Layer - Bottom Layer" at 5694.02,182.74 h60
  text "69 Total" at 4091.16,58.42 h60
  text ".Layer_Name" at 577,-858.49 h60
M17 Embedded Cavity:
  text ".Layer_Name" at 577,-858.49 h60
M18 Embedded Assembly:
  text ".Layer_Name" at 577,-858.49 h60
M19 Embedded Keepout:
  text ".Layer_Name" at 577,-858.49 h60

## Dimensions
0,0 to 3600,0 on M2 Board Dimensions
0,0 to 0,1460 on M2 Board Dimensions
0,-400 to 1000,-400 on M2 Board Dimensions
